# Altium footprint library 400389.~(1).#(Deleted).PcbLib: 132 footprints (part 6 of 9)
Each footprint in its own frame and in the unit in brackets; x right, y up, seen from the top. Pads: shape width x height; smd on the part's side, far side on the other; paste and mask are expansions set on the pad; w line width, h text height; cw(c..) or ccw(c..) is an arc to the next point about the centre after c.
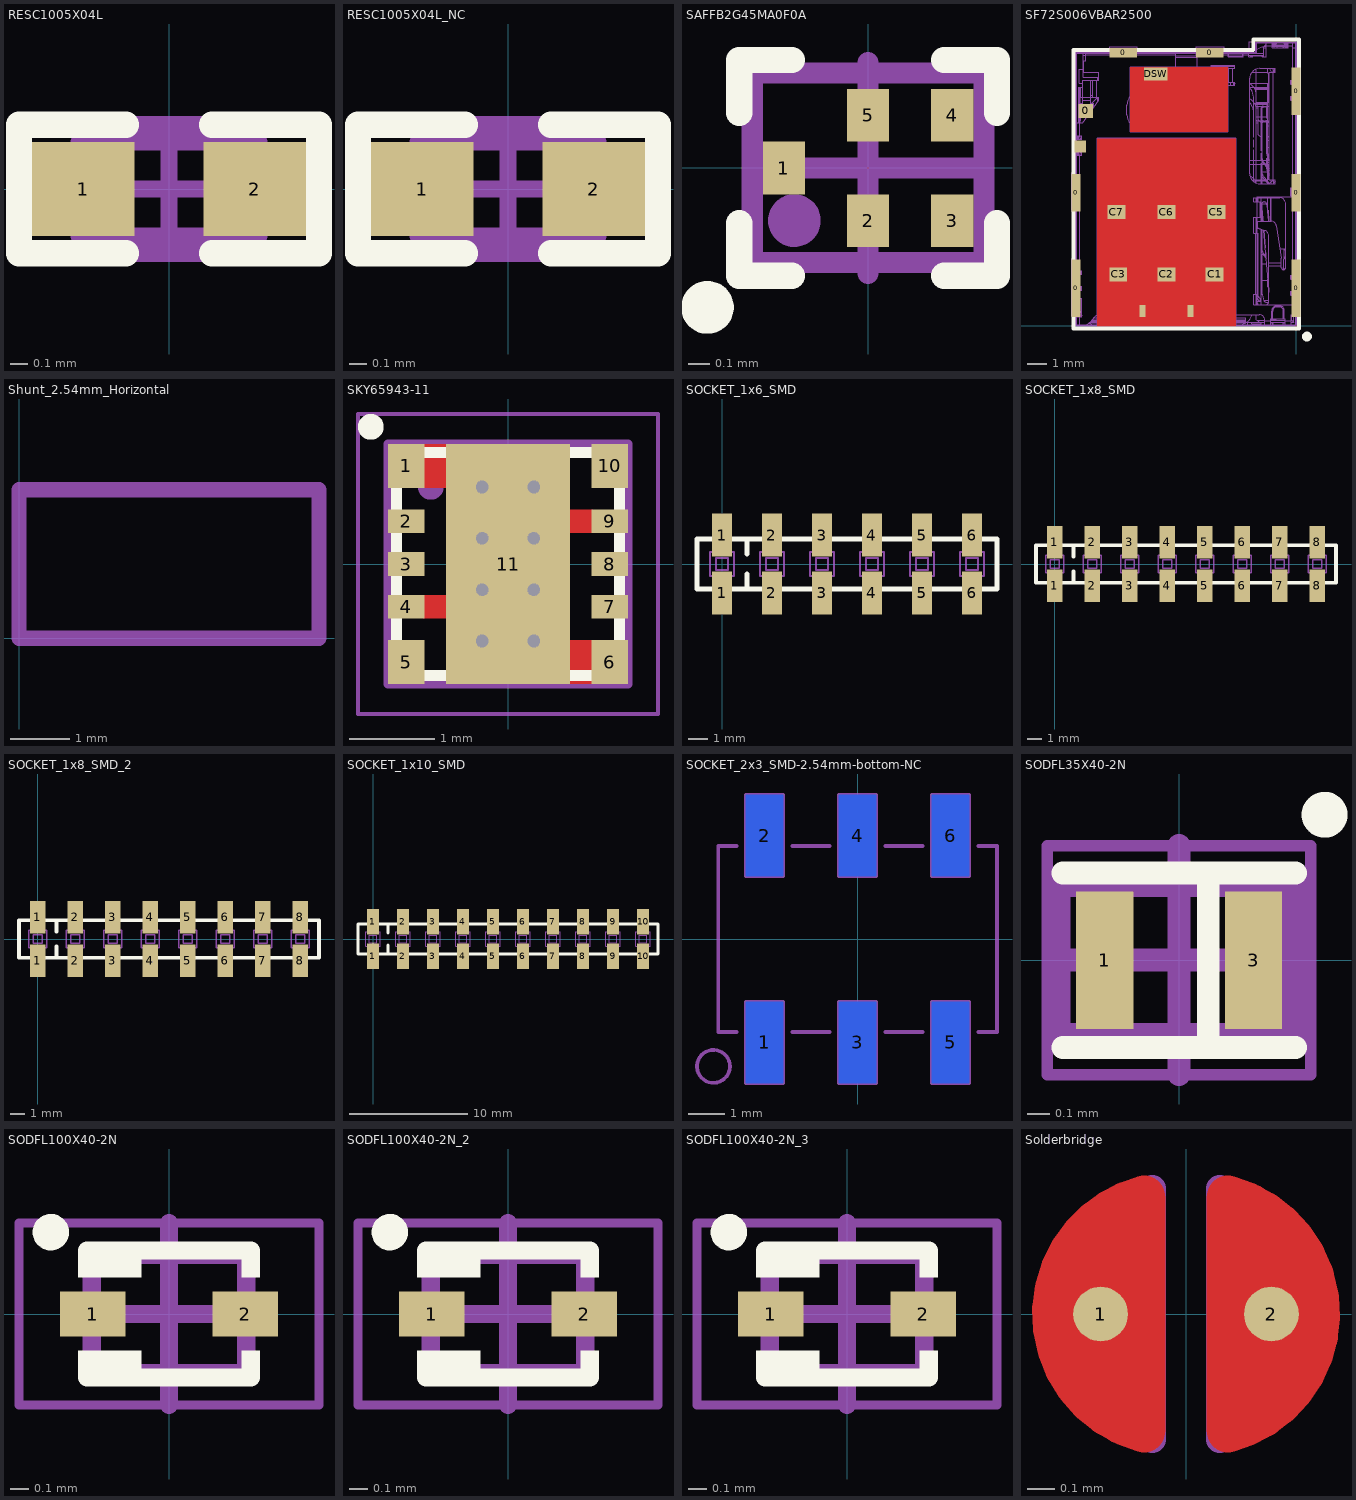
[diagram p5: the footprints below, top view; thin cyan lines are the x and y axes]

## RESC1005X04L [mm]
pads (2):
  rect 0.6x0.55 smd mask+0.05: 1(-0.5,0) 2(0.5,0)
Top Overlay:
  lines w0.152: -0.25,-0.375 -0.875,-0.375 -0.875,0.375 -0.25,0.375 ; 0.25,-0.375 0.875,-0.375 0.875,0.375 0.25,0.375
Mechanical 7:
  lines w0.1: -0.525,-0.275 0.525,-0.275 0.525,0.275 -0.525,0.275 -0.525,-0.275
  text ".Designator" at -0.432,-0.152 h0.3
Mechanical 15:
  lines w0.1: -0.275,0 0.275,0 ; 0,-0.275 0,0.275 ; -0.875,-0.375 -0.875,0.375 0.875,0.375 0.875,-0.375 -0.875,-0.375
3D body "User Library-res0402-1.step": height 0.3, standoff 0, extent -0.5,-0.25 0.5,0.25

## RESC1005X04L_NC [mm]
pads (2):
  rect 0.6x0.55 smd mask+0.05: 1(-0.5,0) 2(0.5,0)
Top Overlay:
  lines w0.152: -0.25,-0.375 -0.875,-0.375 -0.875,0.375 -0.25,0.375 ; 0.25,-0.375 0.875,-0.375 0.875,0.375 0.25,0.375
Mechanical 7:
  lines w0.1: -0.525,-0.275 -0.525,0.275 0.525,0.275 0.525,-0.275 -0.525,-0.275
  text ".Designator" at -0.432,-0.152 h0.3
Mechanical 15:
  lines w0.1: -0.275,0 0.275,0 ; 0,-0.275 0,0.275 ; -0.875,-0.375 0.875,-0.375 0.875,0.375 -0.875,0.375 -0.875,-0.375

## SAFFB2G45MA0F0A [mm]
pads (5):
  rect 0.2x0.25 smd mask+0.065: 1(-0.4,0) 2(0,-0.25) 3(0.4,-0.25) 4(0.4,0.25) 5(0,0.25)
Top Overlay:
  circle w0.15: c-0.762,-0.662 r0.05
  lines w0.125: -0.613,-0.262 -0.613,-0.512 -0.362,-0.512 ; -0.613,0.262 -0.613,0.512 -0.362,0.512 ; 0.362,-0.512 0.613,-0.512 0.613,-0.262 ; 0.362,0.512 0.613,0.512 0.613,0.262
Mechanical 7:
  circle w0.15: c-0.35,-0.25 r0.05
  lines w0.1: -0.55,-0.45 0.55,-0.45 0.55,0.45 -0.55,0.45 -0.55,-0.45
  text ".Designator" at -0.4,0 h0.3
Mechanical 15:
  lines w0.05: -0.55,-0.45 -0.55,0.45 0.55,0.45 0.55,-0.45 -0.55,-0.45
  lines w0.1: -0.5,0 0.5,0 ; 0,-0.5 0,0.5
3D body: height 0.5, standoff 0, extent -0.55,-0.45 0.55,0.45

## SF72S006VBAR2500 [mm]
pads (18):
  rect 0.45x2.9 smd: 0(-11.175,1.9) 0(0,1.9)
  rect 0.45x1.9 smd: 0(-11.175,6.75) 0(0,6.75)
  rect 0.75x0.7 smd: 0(-10.675,10.9)
  rect 1.4x0.5 smd: 0(-8.78,13.85) 0(-4.38,13.85)
  rect 0.3x0.6 smd: 0(-7.8,0.75) 0(-5.36,0.75)
  rect 0.45x2.4 smd: 0(0,11.9)
  rect 0.9x0.7 smd: C1(-4.14,2.6) C2(-6.58,2.6) C3(-9.02,2.6) C5(-4.04,5.77) C6(-6.58,5.77) C7(-9.12,5.77)
  rect 0.6x0.6 smd: CSW(-10.95,9.1)
  rect 1.2x0.65 smd: DSW(-7.13,12.775)
Top Layer:
  pour cut-out: -8.407,13.106 -3.48,13.106 -3.48,9.855 -8.407,9.855
  pour cut-out: -10.084,9.5 -3.073,9.5 -3.073,-0.025 -10.084,-0.025
Top Overlay:
  lines w0.2: -11.3,-0.15 0.15,-0.15 0.15,14.525 -2.175,14.525 -2.175,14 -11.3,14 -11.3,-0.15
  lines w0.25: 0.443,-0.486 ccw(c0.55,-0.55) 0.462,-0.462
Mechanical 7:
  drawing of 1191 lines, arcs and shapes, not listed
  text ".Designator" at -6.214,5.15 h0.38
Mechanical 15:
  lines w0.1: -11.175,0 -11.175,13.85 -2.025,13.85 -2.025,14.375 0,14.375 0,0 -11.175,0 ; -10.08,0 -3.08,0 -3.08,9.5 -10.08,9.5 -10.08,0 ; -8.4,9.85 -8.4,13.1 -3.48,13.1 -3.48,9.85 -8.4,9.85
  text "NO VIA / NO TRACE" at -9.144,7.366 h0.55
  text "NO VIA / NO TRACE" at -8.382,10.668 h0.55
3D body "K3D-SF72S006VBA-V2_JAE_Proprietary.STEP": height 1.25, standoff 0, extent -11.2,0.05 0.02,14.4

## Shunt_2.54mm_Horizontal [mm]
Mechanical 3:
  lines w0.254: 0,0 5.029,0 5.029,2.489 0,2.489 0,0
3D body "User Library-Control System_FCI_68786-102LF.STEP": height 3.04, standoff 0.56, extent 0,-2.54 5.029,2.54

## SKY65943-11 [mm]
pads (12):
  rect 0.425x0.515 smd mask+0.05: 1(-1.188,1.144) 5(-1.188,-1.144) 6(1.188,-1.144) 10(1.188,1.144)
  rect 0.425x0.275 smd mask+0.05: 2(-1.188,0.5) 3(-1.188,0) 4(-1.188,-0.5) 7(1.188,-0.5) 8(1.188,0) 9(1.188,0.5)
  rect 1.45x2.802 smd paste-2 mask-5: 11(0,0)
  rect 1.55x2.487 on Top Solder: ""(0,0)
via -0.3,0.3 diameter 0.35 hole 0.15
via 0.3,0.3 diameter 0.35 hole 0.15
via 0.3,0.9 diameter 0.35 hole 0.15
via -0.3,0.9 diameter 0.35 hole 0.15
via -0.3,-0.3 diameter 0.35 hole 0.15
via 0.3,-0.3 diameter 0.35 hole 0.15
via 0.3,-0.9 diameter 0.35 hole 0.15
via -0.3,-0.9 diameter 0.35 hole 0.15
Top Layer:
  region: -0.712,-0.362 -0.987,-0.362 -0.987,-0.637 -0.712,-0.637
  rectangle: 0.712,0.363 0.987,0.637
  rectangle: 0.712,-1.4 0.987,-0.887
  rectangle: -0.988,0.887 -0.713,1.4
Top Overlay:
  circle w0.2: c-1.6,1.6 r0.05
  lines w0.125: -1.3,-1.3 -1.3,1.3 1.3,1.3 1.3,-1.3 -1.3,-1.3
Top Paste:
  rectangle: -0.774,0.498 0.776,1.243
  rectangle: -0.775,-0.335 0.775,0.335
  rectangle: -0.774,-1.243 0.776,-0.498
Mechanical 7:
  circle w0.2: c-0.9,0.9 r0.05
  lines w0.1: -1.4,-1.4 1.4,-1.4 1.4,1.4 -1.4,1.4 -1.4,-1.4
  text ".Designator" at -0.45,-0.15 h0.3
Mechanical 15:
  lines w0.05: -0.5,0 0.5,0 ; 0,-0.5 0,0.5 ; -1.75,-1.75 -1.75,1.75 1.75,1.75 1.75,-1.75 -1.75,-1.75
3D body: height 0.7, standoff 0, extent -1.25,-1.25 1.25,1.25
3D body: height 0.71, standoff 0.7, extent -1.049,0.75 -0.75,1.05

## SOCKET_1x6_SMD [mm]
pads (12):
  rect 1.02x2.19 smd: 1(0,-1.465) 1(0,1.465) 2(2.54,-1.465) 2(2.54,1.465) 3(5.08,-1.465) 3(5.08,1.465) 4(7.62,-1.465) 4(7.62,1.465) 5(10.16,-1.465) 5(10.16,1.465) 6(12.7,1.465) 6(12.7,-1.465)
Top Overlay:
  lines w0.254: 1.27,-1.27 1.27,-0.508 ; 1.27,0.508 1.27,1.27 ; -1.27,-1.27 -1.27,1.27 13.97,1.27 13.97,-1.27 -1.27,-1.27
Mechanical 7:
  lines w0.1: -0.35,-1.27 -0.35,-1.812 ccw(c0,-1.812) 0.35,-1.812 0.35,-1.27 ; 2.19,1.27 2.19,1.812 cw(c2.54,1.812) 2.89,1.812 2.89,1.27 ; 4.73,-1.27 4.73,-1.812 ccw(c5.08,-1.812) 5.43,-1.812 5.43,-1.27 ; 7.27,1.27 7.27,1.812 cw(c7.62,1.812) 7.97,1.812 7.97,1.27 ; 9.81,-1.27 9.81,-1.812 ccw(c10.16,-1.812) 10.51,-1.812 10.51,-1.27 ; 12.35,1.27 12.35,1.812 cw(c12.7,1.812) 13.05,1.812 13.05,1.27 ; -1.27,-1.27 13.97,-1.27 13.97,1.27 -1.27,1.27 -1.27,-1.27 ; -0.6,-0.6 0.6,-0.6 0.6,0.6 -0.6,0.6 -0.6,-0.6 ; -0.3,-0.3 0.3,-0.3 0.3,0.3 -0.3,0.3 -0.3,-0.3 ; 1.94,-0.6 3.14,-0.6 3.14,0.6 1.94,0.6 1.94,-0.6 ; 2.24,-0.3 2.84,-0.3 2.84,0.3 2.24,0.3 2.24,-0.3 ; 4.48,-0.6 5.68,-0.6 5.68,0.6 4.48,0.6 4.48,-0.6 ; 4.78,-0.3 5.38,-0.3 5.38,0.3 4.78,0.3 4.78,-0.3 ; 7.02,-0.6 8.22,-0.6 8.22,0.6 7.02,0.6 7.02,-0.6 ; 7.32,-0.3 7.92,-0.3 7.92,0.3 7.32,0.3 7.32,-0.3 ; 9.56,-0.6 10.76,-0.6 10.76,0.6 9.56,0.6 9.56,-0.6 ; 9.86,-0.3 10.46,-0.3 10.46,0.3 9.86,0.3 9.86,-0.3 ; 12.1,-0.6 13.3,-0.6 13.3,0.6 12.1,0.6 12.1,-0.6 ; 12.4,-0.3 13,-0.3 13,0.3 12.4,0.3 12.4,-0.3
  text ".Designator" at 0.77,-0.2 h0.38
3D body "Samtec-SSM-106-L-SV.step": height 7.47, standoff -0.03, extent -1.27,-2.286 13.97,2.286

## SOCKET_1x8_SMD [mm]
pads (16):
  rect 1.02x2.19 smd: 1(0,-1.465) 1(0,1.465) 2(2.54,-1.465) 2(2.54,1.465) 3(5.08,-1.465) 3(5.08,1.465) 4(7.62,-1.465) 4(7.62,1.465) 5(10.16,-1.465) 5(10.16,1.465) 6(12.7,1.465) 6(12.7,-1.465) 7(15.24,-1.465) 7(15.24,1.465) 8(17.78,-1.465) 8(17.78,1.465)
Top Overlay:
  lines w0.254: 1.27,-1.27 1.27,-0.508 ; 1.27,0.508 1.27,1.27 ; -1.27,-1.27 -1.27,1.27 19.05,1.27 19.05,-1.27 -1.27,-1.27
Mechanical 7:
  lines w0.1: -0.35,-1.27 -0.35,-1.812 ccw(c0,-1.812) 0.35,-1.812 0.35,-1.27 ; 2.19,1.27 2.19,1.812 cw(c2.54,1.812) 2.89,1.812 2.89,1.27 ; 4.73,-1.27 4.73,-1.812 ccw(c5.08,-1.812) 5.43,-1.812 5.43,-1.27 ; 7.27,1.27 7.27,1.812 cw(c7.62,1.812) 7.97,1.812 7.97,1.27 ; 9.81,-1.27 9.81,-1.812 ccw(c10.16,-1.812) 10.51,-1.812 10.51,-1.27 ; 12.35,1.27 12.35,1.812 cw(c12.7,1.812) 13.05,1.812 13.05,1.27 ; 14.89,-1.27 14.89,-1.812 ccw(c15.24,-1.812) 15.59,-1.812 15.59,-1.27 ; 17.43,1.27 17.43,1.812 cw(c17.78,1.812) 18.13,1.812 18.13,1.27 ; -1.27,-1.27 -1.27,1.27 19.05,1.27 19.05,-1.27 -1.27,-1.27 ; -0.6,-0.6 -0.6,0.6 0.6,0.6 0.6,-0.6 -0.6,-0.6 ; -0.3,-0.3 -0.3,0.3 0.3,0.3 0.3,-0.3 -0.3,-0.3 ; 1.94,-0.6 1.94,0.6 3.14,0.6 3.14,-0.6 1.94,-0.6 ; 2.24,-0.3 2.24,0.3 2.84,0.3 2.84,-0.3 2.24,-0.3 ; 4.48,-0.6 4.48,0.6 5.68,0.6 5.68,-0.6 4.48,-0.6 ; 4.78,-0.3 4.78,0.3 5.38,0.3 5.38,-0.3 4.78,-0.3 ; 7.02,-0.6 7.02,0.6 8.22,0.6 8.22,-0.6 7.02,-0.6 ; 7.32,-0.3 7.32,0.3 7.92,0.3 7.92,-0.3 7.32,-0.3 ; 9.56,-0.6 9.56,0.6 10.76,0.6 10.76,-0.6 9.56,-0.6 ; 9.86,-0.3 9.86,0.3 10.46,0.3 10.46,-0.3 9.86,-0.3 ; 12.1,-0.6 12.1,0.6 13.3,0.6 13.3,-0.6 12.1,-0.6 ; 12.4,-0.3 12.4,0.3 13,0.3 13,-0.3 12.4,-0.3 ; 14.64,-0.6 14.64,0.6 15.84,0.6 15.84,-0.6 14.64,-0.6 ; 14.94,-0.3 14.94,0.3 15.54,0.3 15.54,-0.3 14.94,-0.3 ; 17.18,-0.6 17.18,0.6 18.38,0.6 18.38,-0.6 17.18,-0.6 ; 17.48,-0.3 17.48,0.3 18.08,0.3 18.08,-0.3 17.48,-0.3
  text ".Designator" at 0.77,-0.2 h0.38
3D body "Samtec-SSM-108-L-SV.step": height 7.47, standoff -0.03, extent -1.27,-2.286 19.05,2.286

## SOCKET_1x8_SMD_2 [mm]
pads (16):
  rect 1.02x2.19 smd: 1(0,-1.465) 1(0,1.465) 2(2.54,-1.465) 2(2.54,1.465) 3(5.08,-1.465) 3(5.08,1.465) 4(7.62,-1.465) 4(7.62,1.465) 5(10.16,-1.465) 5(10.16,1.465) 6(12.7,1.465) 6(12.7,-1.465) 7(15.24,-1.465) 7(15.24,1.465) 8(17.78,-1.465) 8(17.78,1.465)
Top Overlay:
  lines w0.254: 1.27,-1.27 1.27,-0.508 ; 1.27,0.508 1.27,1.27 ; -1.27,-1.27 -1.27,1.27 19.05,1.27 19.05,-1.27 -1.27,-1.27
Mechanical 7:
  lines w0.1: -0.35,-1.27 -0.35,-1.812 ccw(c0,-1.812) 0.35,-1.812 0.35,-1.27 ; 2.19,1.27 2.19,1.812 cw(c2.54,1.812) 2.89,1.812 2.89,1.27 ; 4.73,-1.27 4.73,-1.812 ccw(c5.08,-1.812) 5.43,-1.812 5.43,-1.27 ; 7.27,1.27 7.27,1.812 cw(c7.62,1.812) 7.97,1.812 7.97,1.27 ; 9.81,-1.27 9.81,-1.812 ccw(c10.16,-1.812) 10.51,-1.812 10.51,-1.27 ; 12.35,1.27 12.35,1.812 cw(c12.7,1.812) 13.05,1.812 13.05,1.27 ; 14.89,-1.27 14.89,-1.812 ccw(c15.24,-1.812) 15.59,-1.812 15.59,-1.27 ; 17.43,1.27 17.43,1.812 cw(c17.78,1.812) 18.13,1.812 18.13,1.27 ; -1.27,-1.27 -1.27,1.27 19.05,1.27 19.05,-1.27 -1.27,-1.27 ; -0.6,-0.6 -0.6,0.6 0.6,0.6 0.6,-0.6 -0.6,-0.6 ; -0.3,-0.3 -0.3,0.3 0.3,0.3 0.3,-0.3 -0.3,-0.3 ; 1.94,-0.6 1.94,0.6 3.14,0.6 3.14,-0.6 1.94,-0.6 ; 2.24,-0.3 2.24,0.3 2.84,0.3 2.84,-0.3 2.24,-0.3 ; 4.48,-0.6 4.48,0.6 5.68,0.6 5.68,-0.6 4.48,-0.6 ; 4.78,-0.3 4.78,0.3 5.38,0.3 5.38,-0.3 4.78,-0.3 ; 7.02,-0.6 7.02,0.6 8.22,0.6 8.22,-0.6 7.02,-0.6 ; 7.32,-0.3 7.32,0.3 7.92,0.3 7.92,-0.3 7.32,-0.3 ; 9.56,-0.6 9.56,0.6 10.76,0.6 10.76,-0.6 9.56,-0.6 ; 9.86,-0.3 9.86,0.3 10.46,0.3 10.46,-0.3 9.86,-0.3 ; 12.1,-0.6 12.1,0.6 13.3,0.6 13.3,-0.6 12.1,-0.6 ; 12.4,-0.3 12.4,0.3 13,0.3 13,-0.3 12.4,-0.3 ; 14.64,-0.6 14.64,0.6 15.84,0.6 15.84,-0.6 14.64,-0.6 ; 14.94,-0.3 14.94,0.3 15.54,0.3 15.54,-0.3 14.94,-0.3 ; 17.18,-0.6 17.18,0.6 18.38,0.6 18.38,-0.6 17.18,-0.6 ; 17.48,-0.3 17.48,0.3 18.08,0.3 18.08,-0.3 17.48,-0.3
  text ".Designator" at 0.77,-0.2 h0.38
3D body "Samtec-SSM-108-L-SV.step": height 7.47, standoff -0.03, extent -1.27,-2.286 19.05,2.286

## SOCKET_1x10_SMD [mm]
pads (20):
  rect 1.02x2.19 smd: 1(0,-1.465) 1(0,1.465) 2(2.54,-1.465) 2(2.54,1.465) 3(5.08,-1.465) 3(5.08,1.465) 4(7.62,-1.465) 4(7.62,1.465) 5(10.16,-1.465) 5(10.16,1.465) 6(12.7,-1.465) 6(12.7,1.465) 7(15.24,-1.465) 7(15.24,1.465) 8(17.78,-1.465) 8(17.78,1.465) 9(20.32,-1.465) 9(20.32,1.465) 10(22.86,-1.465) 10(22.86,1.465)
Top Overlay:
  lines w0.254: 1.27,-1.27 1.27,-0.508 ; 1.27,0.508 1.27,1.27 ; -1.27,-1.27 -1.27,1.27 24.13,1.27 24.13,-1.27 -1.27,-1.27
Mechanical 7:
  lines w0.1: -0.35,-1.27 -0.35,-1.812 ccw(c0,-1.812) 0.35,-1.812 0.35,-1.27 ; 2.19,1.27 2.19,1.812 cw(c2.54,1.812) 2.89,1.812 2.89,1.27 ; 4.73,-1.27 4.73,-1.812 ccw(c5.08,-1.812) 5.43,-1.812 5.43,-1.27 ; 7.27,1.27 7.27,1.812 cw(c7.62,1.812) 7.97,1.812 7.97,1.27 ; 9.81,-1.27 9.81,-1.812 ccw(c10.16,-1.812) 10.51,-1.812 10.51,-1.27 ; 12.35,1.27 12.35,1.812 cw(c12.7,1.812) 13.05,1.812 13.05,1.27 ; 14.89,-1.27 14.89,-1.812 ccw(c15.24,-1.812) 15.59,-1.812 15.59,-1.27 ; 17.43,1.27 17.43,1.812 cw(c17.78,1.812) 18.13,1.812 18.13,1.27 ; 19.97,-1.27 19.97,-1.812 ccw(c20.32,-1.812) 20.67,-1.812 20.67,-1.27 ; 22.51,1.27 22.51,1.812 cw(c22.86,1.812) 23.21,1.812 23.21,1.27 ; -1.27,-1.27 24.13,-1.27 24.13,1.27 -1.27,1.27 -1.27,-1.27 ; -0.6,-0.6 0.6,-0.6 0.6,0.6 -0.6,0.6 -0.6,-0.6 ; -0.3,-0.3 0.3,-0.3 0.3,0.3 -0.3,0.3 -0.3,-0.3 ; 1.94,-0.6 3.14,-0.6 3.14,0.6 1.94,0.6 1.94,-0.6 ; 2.24,-0.3 2.84,-0.3 2.84,0.3 2.24,0.3 2.24,-0.3 ; 4.48,-0.6 5.68,-0.6 5.68,0.6 4.48,0.6 4.48,-0.6 ; 4.78,-0.3 5.38,-0.3 5.38,0.3 4.78,0.3 4.78,-0.3 ; 7.02,-0.6 8.22,-0.6 8.22,0.6 7.02,0.6 7.02,-0.6 ; 7.32,-0.3 7.92,-0.3 7.92,0.3 7.32,0.3 7.32,-0.3 ; 9.56,-0.6 10.76,-0.6 10.76,0.6 9.56,0.6 9.56,-0.6 ; 9.86,-0.3 10.46,-0.3 10.46,0.3 9.86,0.3 9.86,-0.3 ; 12.1,-0.6 13.3,-0.6 13.3,0.6 12.1,0.6 12.1,-0.6 ; 12.4,-0.3 13,-0.3 13,0.3 12.4,0.3 12.4,-0.3 ; 14.64,-0.6 15.84,-0.6 15.84,0.6 14.64,0.6 14.64,-0.6 ; 14.94,-0.3 15.54,-0.3 15.54,0.3 14.94,0.3 14.94,-0.3 ; 17.18,-0.6 18.38,-0.6 18.38,0.6 17.18,0.6 17.18,-0.6 ; 17.48,-0.3 18.08,-0.3 18.08,0.3 17.48,0.3 17.48,-0.3 ; 19.72,-0.6 20.92,-0.6 20.92,0.6 19.72,0.6 19.72,-0.6 ; 20.02,-0.3 20.62,-0.3 20.62,0.3 20.02,0.3 20.02,-0.3 ; 22.26,-0.6 23.46,-0.6 23.46,0.6 22.26,0.6 22.26,-0.6 ; 22.56,-0.3 23.16,-0.3 23.16,0.3 22.56,0.3 22.56,-0.3
  text ".Designator" at 0.77,-0.2 h0.38
3D body "Samtec-SSM-110-L-SV.step": height 7.47, standoff -0.03, extent -1.27,-2.286 24.13,2.286

## SOCKET_2x3_SMD-2.54mm-bottom-NC [mm]
pads (6):
  rect 1.02x2.22 smd far side: 1(-2.54,-2.825) 2(-2.54,2.825) 3(0,-2.825) 4(0,2.825) 5(2.54,-2.825) 6(2.54,2.825)
Bottom Overlay:
  circle w0.508: c-3.936,-3.48 r0.254
  lines w0.254: -3.33,-2.54 -3.81,-2.54 -3.81,2.54 -3.33,2.54 ; -1.77,-2.54 -0.78,-2.54 ; -1.77,2.54 -0.78,2.54 ; 0.78,-2.54 1.77,-2.54 ; 0.78,2.54 1.77,2.54 ; 3.33,-2.54 3.81,-2.54 3.81,2.54 3.33,2.54
Mechanical 8:
  circle w0.1: c-3.936,-3.48 r0.45
  lines w0.1: -3.302,-2.54 -3.81,-2.54 -3.81,2.54 -3.302,2.54 ; -1.778,-2.54 -0.762,-2.54 ; -1.778,2.54 -0.762,2.54 ; 0.762,-2.54 1.778,-2.54 ; 0.762,2.54 1.778,2.54 ; 3.302,-2.54 3.81,-2.54 3.81,2.54 3.302,2.54 ; -3.05,-3.935 -3.05,-1.715 -2.03,-1.715 -2.03,-3.935 -3.05,-3.935 ; -3.05,1.715 -2.03,1.715 -2.03,3.935 -3.05,3.935 -3.05,1.715 ; -0.51,-3.935 -0.51,-1.715 0.51,-1.715 0.51,-3.935 -0.51,-3.935 ; -0.51,1.715 -0.51,3.935 0.51,3.935 0.51,1.715 -0.51,1.715 ; 2.03,-3.935 2.03,-1.715 3.05,-1.715 3.05,-3.935 2.03,-3.935 ; 2.03,1.715 2.03,3.935 3.05,3.935 3.05,1.715 2.03,1.715
  text ".Designator" at -3.226,0.178 h0.38

## SODFL35X40-2N [mm]
pads (2):
  rect 0.25x0.6 smd: 1(-0.325,0) 3(0.325,0)
Top Overlay:
  circle w0.1: c0.635,0.635 r0.05
  lines w0.1: -0.508,-0.381 0.508,-0.381 ; -0.508,0.381 0.508,0.381 ; 0.127,-0.381 0.127,0.381
Mechanical 7:
  rectangle: 0.3,-0.3 0.5,0.3
  lines w0.05: -0.5,-0.3 0.5,-0.3 0.5,0.3 -0.5,0.3 -0.5,-0.3
  text ".Designator" at -0.425,-0.15 h0.3
Mechanical 13:
  lines w0.1: -0.525,-0.325 -0.525,0.325 0.525,0.325 0.525,-0.325 -0.525,-0.325
Mechanical 15:
  lines w0.05: -0.575,-0.5 0.575,-0.5 0.575,0.5 -0.575,0.5 -0.575,-0.5
  lines w0.1: -0.5,0 0.5,0 ; 0,-0.5 0,0.5
3D body: height 0.4, standoff 0, extent -0.525,-0.325 0.525,0.325

## SODFL100X40-2N [mm]
pads (2):
  rect 0.36x0.25 smd: 1(-0.42,0) 2(0.42,0)
Top Overlay:
  circle w0.1: c-0.65,0.45 r0.05
  rectangle: 0.4,0.2 0.5,0.35
  rectangle: 0.4,-0.35 0.5,-0.2
  rectangle: -0.5,-0.35 -0.15,-0.2
  rectangle: -0.5,0.2 -0.15,0.325
  lines w0.1: -0.45,-0.3 -0.45,-0.35 0.45,-0.35 0.45,-0.3 ; -0.45,0.3 -0.45,0.35 0.45,0.35 0.45,0.3
Mechanical 7:
  lines w0.1: -0.425,-0.325 -0.425,0.325 0.425,0.325 0.425,-0.325 -0.425,-0.325
  text ".Designator" at -0.724,-0.177 h0.38
Mechanical 15:
  lines w0.05: -0.825,-0.5 0.825,-0.5 0.825,0.5 -0.825,0.5 -0.825,-0.5
  lines w0.1: -0.5,0 0.5,0 ; 0,-0.5 0,0.5
3D body "SODFL100X40-2N.step": height 0.4, standoff 0, extent -0.5,-0.325 0.5,0.325

## SODFL100X40-2N_2 [mm]
pads (2):
  rect 0.36x0.25 smd: 1(-0.42,0) 2(0.42,0)
Top Overlay:
  circle w0.1: c-0.65,0.45 r0.05
  rectangle: 0.4,0.2 0.5,0.35
  rectangle: 0.4,-0.35 0.5,-0.2
  rectangle: -0.5,-0.35 -0.15,-0.2
  rectangle: -0.5,0.2 -0.15,0.325
  lines w0.1: -0.45,-0.3 -0.45,-0.35 0.45,-0.35 0.45,-0.3 ; -0.45,0.3 -0.45,0.35 0.45,0.35 0.45,0.3
Mechanical 7:
  lines w0.1: -0.425,-0.325 -0.425,0.325 0.425,0.325 0.425,-0.325 -0.425,-0.325
  text ".Designator" at -0.724,-0.177 h0.38
Mechanical 15:
  lines w0.05: -0.825,-0.5 0.825,-0.5 0.825,0.5 -0.825,0.5 -0.825,-0.5
  lines w0.1: -0.5,0 0.5,0 ; 0,-0.5 0,0.5
3D body "SODFL100X40-2N.step": height 0.4, standoff 0, extent -0.5,-0.325 0.5,0.325

## SODFL100X40-2N_3 [mm]
pads (2):
  rect 0.36x0.25 smd: 1(-0.42,0) 2(0.42,0)
Top Overlay:
  circle w0.1: c-0.65,0.45 r0.05
  rectangle: 0.4,0.2 0.5,0.35
  rectangle: 0.4,-0.35 0.5,-0.2
  rectangle: -0.5,-0.35 -0.15,-0.2
  rectangle: -0.5,0.2 -0.15,0.325
  lines w0.1: -0.45,-0.3 -0.45,-0.35 0.45,-0.35 0.45,-0.3 ; -0.45,0.3 -0.45,0.35 0.45,0.35 0.45,0.3
Mechanical 7:
  lines w0.1: -0.425,-0.325 -0.425,0.325 0.425,0.325 0.425,-0.325 -0.425,-0.325
  text ".Designator" at -0.724,-0.177 h0.38
Mechanical 15:
  lines w0.05: -0.825,-0.5 0.825,-0.5 0.825,0.5 -0.825,0.5 -0.825,-0.5
  lines w0.1: -0.5,0 0.5,0 ; 0,-0.5 0,0.5
3D body "SODFL100X40-2N.step": height 0.4, standoff 0, extent -0.5,-0.325 0.5,0.325

## Solderbridge [mm]
pads (2):
  round 0.2 smd paste-10: 1(-0.312,0) 2(0.312,0)
Top Layer:
  region: 0.077,0.432 0.152,0.505 0.271,0.467 0.335,0.424 0.409,0.351 0.462,0.292 0.521,0.193 0.549,0.099 0.544,-0.122 0.518,-0.193 0.434,-0.33 0.351,-0.411 0.259,-0.469 0.157,-0.5 0.107,-0.483 0.077,-0.43
  region: -0.077,-0.432 -0.152,-0.505 -0.271,-0.467 -0.335,-0.424 -0.409,-0.351 -0.462,-0.292 -0.521,-0.193 -0.549,-0.099 -0.544,0.122 -0.518,0.193 -0.434,0.33 -0.351,0.411 -0.259,0.469 -0.157,0.5 -0.107,0.483 -0.077,0.43
  lines w0.152: -0.153,-0.431 cw(c-0.042,0) -0.42,0.235 cw(c-0.042,0) -0.153,0.431 ; 0.153,-0.431 ccw(c0.042,0) 0.468,0.13 ccw(c0.042,0) 0.461,0.149 ccw(c0.042,0) 0.153,0.431
Top Solder:
  circle w0.61: c-0.003,0 r0.279
Mechanical 7:
  lines w0.1: -0.123,-0.459 cw(c-0.042,0) -0.123,0.459 -0.123,-0.459 ; 0.123,-0.459 ccw(c0.042,0) 0.123,0.459 0.123,-0.459
  text ".Designator" at -0.635,0.635 h0.38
